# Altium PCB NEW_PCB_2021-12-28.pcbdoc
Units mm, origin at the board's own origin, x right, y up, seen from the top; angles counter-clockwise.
Board outline 29.65 x 29.79 mm, 2 copper layers (Top Layer, Bottom Layer); 1 components, 0 nets, 6 pads, 0 vias.
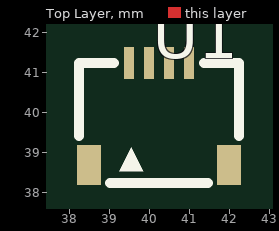
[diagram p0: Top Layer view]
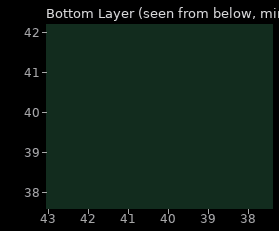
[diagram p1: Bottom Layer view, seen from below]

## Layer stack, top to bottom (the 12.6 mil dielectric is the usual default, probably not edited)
Top Layer: signal copper (thickness not stored)
Dielectric: dielectric 0.32, FR-4, Dk 4.8
Bottom Layer: signal copper (thickness not stored)

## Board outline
55.054,25.4 25.4,25.4 25.4,55.191 55.054,55.191

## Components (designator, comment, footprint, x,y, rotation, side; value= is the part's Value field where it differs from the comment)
U1 "FFC-SMD_4P-P0.50_AFC42-S04FMA-1H" FFC-SMD_4P-P0.50_AFC42-S04FMA-1H 40.227,39.952 r0 top

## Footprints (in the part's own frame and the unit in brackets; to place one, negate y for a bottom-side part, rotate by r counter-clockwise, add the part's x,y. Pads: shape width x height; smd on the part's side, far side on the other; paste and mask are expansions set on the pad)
FFC-SMD_4P-P0.50_AFC42-S04FMA-1H [mm]
  rect 0.25x0.8 smd: 1(-0.75,1.275) 2(-0.25,1.275) 3(0.25,1.275) 4(0.75,1.275)
  rect 0.6x1 smd: 5(1.75,-1.275) 6(-1.75,-1.275)
  silkscreen extent -2,-1.72 2,1.28

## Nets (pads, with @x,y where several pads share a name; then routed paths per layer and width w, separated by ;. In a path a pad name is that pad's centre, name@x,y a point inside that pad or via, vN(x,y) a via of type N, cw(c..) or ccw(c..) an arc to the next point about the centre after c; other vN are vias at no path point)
pads on no net: U1.1 U1.2 U1.3 U1.4 U1.5 U1.6

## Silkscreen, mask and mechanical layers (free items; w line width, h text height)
Document:
  lines w0.003: 40.202,40.27 40.252,40.321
